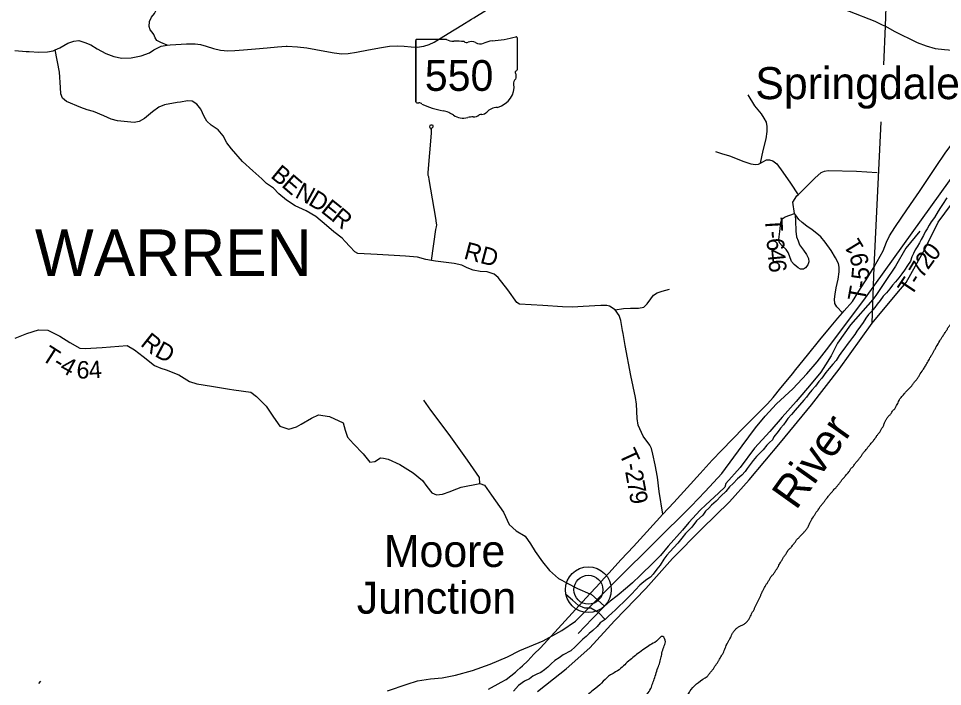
# Model space of a CAD drawing. Extents: x -84548 to 2262448, y -162180 to 525962.
# Drawn here: x 26368 to 42243, y 86581 to 98053 of the extents above; entities that cross this region are included whole.
import ezdxf

# ---------------------------------------------------------------- set-up
doc = ezdxf.new("R2010")
doc.units = 0
for name, color, linetype in [('GM_X_Adjacent_County_Text', 7, 'Continuous'), ('GM_X_City_Street', 7, 'Continuous'), ('GM_X_Corporation_Text', 7, 'Continuous'), ('GM_X_Hydro', 7, 'Continuous'), ('GM_X_Interstate_Location', 7, 'Continuous'), ('GM_X_Major_Lake_Text', 7, 'Continuous'), ('GM_X_Major_River', 7, 'Continuous'), ('GM_X_Minor_Lake', 7, 'Continuous'), ('GM_X_Rail_Line', 7, 'Continuous'), ('GM_X_State_Route', 7, 'Continuous'), ('GM_X_Township_Road', 7, 'Continuous'), ('GM_X_Township_ROW', 7, 'Continuous'), ('GM_X_Unincorporated_Location', 7, 'Continuous')]:
    doc.layers.add(name, color=color, linetype=linetype)

msp = doc.modelspace()

# ---------------------------------------------------------------- linework, layer by layer
at = {"layer": 'GM_X_City_Street'}
msp.add_line((41032, 92821), (41457, 93329), dxfattribs=at)
at = {"layer": 'GM_X_Hydro'}
for p, q in [((41265, 97920), (41693, 109574)), ((41234, 97255), (41265, 97920)), ((41070, 93787), (41188, 96276)), ((42169, 94557), (42676, 95246)), ((41940, 94093), (42169, 94557)), ((41616, 93517), (41940, 94093)), ((41032, 92821), (41070, 93787)), ((41457, 93329), (41616, 93517)), ((40467, 92029), (41032, 92821)), ((39990, 91416), (40467, 92029)), ((39460, 90770), (39990, 91416)), ((38921, 90130), (39460, 90770)), ((38585, 89751), (38921, 90130)), ((38110, 89287), (38585, 89751)), ((37603, 88778), (38110, 89287)), ((37145, 88264), (37603, 88778)), ((36609, 87712), (37145, 88264)), ((36186, 87243), (36609, 87712)), ((35780, 86887), (36186, 87243)), ((35558, 86715), (35780, 86887)), ((35286, 86497), (35558, 86715))]:
    msp.add_line(p, q, dxfattribs=at)
at = {"layer": 'GM_X_Interstate_Location'}
for points in [[(42315, 94974), (42241, 94857), (42207, 94806), (42168, 94747), (42106, 94638), (42051, 94563), (42012, 94506), (41977, 94439), (41946, 94387), (41917, 94328), (41876, 94259), (41847, 94198), (41810, 94130), (41774, 94079), (41745, 94018), (41718, 93958), (41695, 93885), (41644, 93812), (41588, 93731), (41543, 93670), (41492, 93599), (41435, 93532), (41386, 93475), (41339, 93412), (41282, 93343), (41226, 93282), (41174, 93208), (41120, 93147), (41081, 93089), (41026, 93024), (40973, 92969), (40926, 92906), (40879, 92831), (40834, 92768), (40773, 92684), (40738, 92628), (40699, 92573), (40644, 92504), (40603, 92453), (40564, 92396), (40527, 92345), (40466, 92264), (40415, 92181), (40360, 92116), (40295, 92041), (40238, 91972), (40168, 91876), (40120, 91817), (40062, 91740), (39997, 91671), (39948, 91608), (39906, 91553), (39859, 91500), (39789, 91413), (39710, 91325), (39649, 91254), (39588, 91185), (39553, 91134), (39510, 91075)], [(39510, 91075), (39460, 91020), (39419, 90961), (39347, 90870), (39323, 90819), (39272, 90774), (39227, 90724), (39160, 90648), (39103, 90589), (39050, 90532), (38991, 90461), (38936, 90392), (38885, 90327), (38852, 90276), (38793, 90209), (38721, 90146), (38647, 90068), (38583, 90009), (38521, 89930), (38440, 89858), (38353, 89767), (38272, 89695), (38227, 89644), (38174, 89595), (38125, 89526), (38018, 89426), (37936, 89316), (37881, 89263), (37829, 89210), (37765, 89127), (37696, 89044), (37627, 88970), (37560, 88895), (37509, 88836), (37454, 88767), (37390, 88664), (37335, 88595), (37270, 88511), (37225, 88458), (37165, 88419), (37110, 88378), (37041, 88319), (36968, 88244), (36907, 88174), (36848, 88113), (36759, 88026), (36694, 87964), (36617, 87893), (36566, 87844), (36498, 87785), (36445, 87734), (36364, 87674), (36311, 87613), (36236, 87544), (36171, 87494), (36123, 87442), (36062, 87392), (35993, 87327), (35930, 87262), (35859, 87195), (35727, 87125)], [(35727, 87125), (35656, 87076), (35580, 87030), (35517, 86971), (35464, 86912), (35408, 86868), (35343, 86823), (35275, 86792), (35205, 86761), (35146, 86711)], [(35146, 86711), (35062, 86674), (34958, 86601), (34871, 86500)]]:
    msp.add_lwpolyline(points, dxfattribs=at)
for points in [[(41241, 91094), (41263, 91144), (41287, 91185), (41320, 91229), (41360, 91271), (41382, 91311), (41422, 91350), (41446, 91394), (41481, 91454), (41497, 91495), (41531, 91545), (41583, 91605), (41616, 91646), (41672, 91698), (41716, 91745), (41744, 91789), (41785, 91837), (41821, 91884), (41847, 91928), (41907, 92018), (41944, 92077), (41976, 92131), (42006, 92183), (42028, 92224), (42057, 92276), (42081, 92318), (42107, 92361), (42137, 92415), (42196, 92515), (42226, 92564), (42254, 92606), (42287, 92658), (42315, 92699), (42337, 92741), (42371, 92789), (42400, 92831), (42434, 92890), (42470, 92940), (42508, 92997), (42543, 93045), (42575, 93089), (42607, 93132), (42637, 93174), (42665, 93216), (42692, 93256), (42726, 93303), (42754, 93343), (42794, 93401), (42824, 93442), (42855, 93482), (42891, 93522), (42927, 93573), (42975, 93627), (43008, 93669), (43048, 93724), (43088, 93774), (43154, 93863), (43185, 93907), (43231, 93965), (43267, 94010), (43317, 94068), (43358, 94115), (43410, 94171), (43450, 94213), (43480, 94254), (43522, 94278), (43563, 94318), (43611, 94355), (43653, 94393), (43721, 94464), (43765, 94500), (43808, 94550), (43852, 94605), (43884, 94653), (43930, 94721), (43967, 94770), (44033, 94858), (44077, 94911), (44111, 94955), (44140, 95001), (44176, 95042), (44210, 95084), (44256, 95134), (44296, 95173), (44335, 95213), (44389, 95264), (44433, 95310), (44473, 95354), (44513, 95397), (44558, 95445), (44606, 95493), (44656, 95542), (44706, 95590), (44747, 95629), (44787, 95665), (44845, 95713), (44891, 95752)], [(38202, 86755), (38234, 86797), (38268, 86839), (38307, 86886), (38331, 86928), (38363, 86970), (38387, 87010), (38413, 87051), (38460, 87131), (38484, 87175), (38502, 87220), (38518, 87262), (38535, 87304), (38559, 87348), (38585, 87391), (38611, 87439), (38628, 87485), (38656, 87525), (38694, 87570), (38738, 87604), (38782, 87628), (38824, 87647), (38870, 87681), (38909, 87725), (38935, 87766), (38955, 87808), (38971, 87852), (39001, 87892), (39020, 87937), (39042, 87983), (39064, 88029), (39109, 88122), (39129, 88168), (39151, 88216), (39175, 88260), (39196, 88301), (39222, 88343), (39248, 88383), (39278, 88431), (39302, 88472), (39337, 88512), (39367, 88556), (39395, 88597), (39423, 88643), (39443, 88683), (39474, 88735), (39498, 88778), (39530, 88824), (39564, 88874), (39595, 88927), (39635, 88965), (39673, 89013), (39711, 89058), (39735, 89098), (39778, 89142), (39820, 89187), (39860, 89225), (39894, 89267), (39928, 89310), (39951, 89366), (39973, 89412), (40025, 89493), (40054, 89543), (40080, 89583), (40118, 89630), (40144, 89674), (40182, 89720), (40213, 89760), (40245, 89803), (40287, 89855), (40323, 89899), (40360, 89942), (40408, 89996), (40446, 90039), (40484, 90083), (40516, 90133), (40557, 90178), (40599, 90226), (40643, 90280), (40671, 90323), (40713, 90367), (40746, 90417), (40792, 90468), (40826, 90512), (40856, 90554), (40887, 90599), (40929, 90649), (40963, 90691), (40995, 90732), (41041, 90786), (41072, 90826), (41110, 90879), (41140, 90919), (41172, 90961), (41193, 91004), (41223, 91048), (41241, 91094)], [(35751, 85218), (36117, 85474), (36217, 85576), (36310, 85654), (36386, 85744), (36466, 85853), (36547, 85943), (36634, 86004), (36756, 86093), (36859, 86157), (36948, 86202), (37035, 86268), (37101, 86357), (37185, 86471), (37242, 86572), (37272, 86663), (37308, 86757), (37342, 86876), (37381, 86973), (37405, 87067), (37423, 87154), (37454, 87259), (37482, 87349), (37436, 87442), (37328, 87360), (37219, 87296), (37126, 87231), (37009, 87146), (36925, 87077), (36826, 86999), (36740, 86913), (36627, 86831), (36540, 86782), (36416, 86671), (36290, 86555), (36197, 86481), (36079, 86379), (35970, 86303), (35879, 86245), (35795, 86124)], [(35799, 84357), (36082, 84623), (36161, 84710), (36247, 84796), (36340, 84874), (36440, 84970), (36538, 85065), (36621, 85155), (36761, 85280), (36877, 85356), (36962, 85421), (37060, 85519), (37139, 85607), (37215, 85696), (37296, 85784), (37403, 85908), (37480, 85997), (37556, 86101), (37658, 86215), (37754, 86317), (37862, 86435), (37925, 86528), (38202, 86755)]]:
    msp.add_spline(points, degree=3, dxfattribs=at)
at = {"layer": 'GM_X_Major_Lake_Text'}
for points in [[(34151, 98041), (34152, 98041), (34193, 98065), (34404, 98198), (34535, 98275), (34649, 98346), (34744, 98399), (34838, 98436), (34912, 98448), (34941, 98449)], [(39394, 98410), (39449, 98404), (39548, 98394), (39742, 98375), (39885, 98355), (39912, 98350), (40045, 98328), (40231, 98281), (40412, 98254), (40638, 98179), (41078, 98005), (41159, 97968)], [(30968, 97577), (30986, 97579), (31164, 97566), (31324, 97552), (31477, 97521), (31629, 97492), (31789, 97463), (31925, 97447), (32033, 97450), (32175, 97475), (32383, 97513), (32604, 97555), (32744, 97576), (32876, 97581), (32996, 97578), (33112, 97567), (33220, 97560), (33332, 97577), (33424, 97606), (33511, 97647), (33748, 97795), (33984, 97941), (34151, 98041)], [(41159, 97968), (41209, 97946)], [(41209, 97946), (41265, 97920), (41412, 97837), (41809, 97640), (41965, 97585), (42115, 97536), (42277, 97520), (42415, 97509), (42543, 97506), (42681, 97519), (42746, 97529), (42753, 97530)], [(26546, 97484), (26549, 97484), (26719, 97476), (26864, 97479), (26962, 97496), (27001, 97513), (27080, 97548), (27217, 97627), (27321, 97666), (27407, 97673), (27507, 97643), (27609, 97600), (27722, 97533), (27870, 97451), (28004, 97398), (28144, 97371), (28304, 97378), (28476, 97413), (28617, 97462), (28695, 97514), (28739, 97539), (28822, 97576), (28924, 97597), (28977, 97600)], [(26303, 97501), (26503, 97487), (26546, 97484)], [(28977, 97600), (28977, 97600), (29072, 97606), (29252, 97618), (29402, 97619), (29496, 97604), (29592, 97580), (29721, 97535), (29839, 97510), (29965, 97496), (30085, 97501), (30235, 97516), (30443, 97530), (30640, 97552), (30816, 97565), (30968, 97577)], [(41071, 93789), (41226, 94063), (41281, 94211), (41334, 94322), (41425, 94461), (41543, 94640), (41692, 94857), (41848, 95081), (41985, 95286), (42135, 95512), (42291, 95741), (42420, 95920), (42515, 96021), (42618, 96132), (42753, 96263), (42893, 96393), (43071, 96560), (43179, 96665), (43240, 96744), (43293, 96812), (43432, 96986), (43512, 97094), (43534, 97123)], [(39612, 91886), (39665, 91952), (39726, 92026), (39925, 92270), (40137, 92534), (40304, 92736), (40442, 92909), (40523, 92999), (40553, 93034), (40694, 93195), (40835, 93417), (40933, 93565), (41070, 93787), (41071, 93789)], [(36430, 88440), (36431, 88441), (36510, 88528), (36725, 88760), (36935, 88988), (37165, 89238), (37439, 89543), (37629, 89741), (37856, 89995), (38080, 90237), (38286, 90469), (38451, 90640), (38638, 90828), (38830, 91028), (39043, 91242), (39239, 91437), (39334, 91542), (39467, 91708), (39612, 91886)], [(34986, 86900), (35029, 86939), (35120, 87025), (35223, 87134), (35336, 87247), (36186, 88174), (36300, 88296), (36430, 88440)], [(34445, 86536), (34662, 86654), (34744, 86701), (34905, 86828), (34937, 86856), (34986, 86900)]]:
    msp.add_lwpolyline(points, dxfattribs=at)
at = {"layer": 'GM_X_Major_River'}
for radius in [393, 249]:
    msp.add_circle((36159, 88244), radius, dxfattribs=at)
at = {"layer": 'GM_X_Minor_Lake'}
for points in [[(28924, 97597), (28816, 97641), (28746, 97673), (28718, 97721), (28695, 97781), (28667, 97817), (28629, 97861), (28615, 97917), (28622, 98001), (28652, 98073), (28703, 98140), (28731, 98198), (28762, 98310), (28784, 98453), (28797, 98565), (28806, 98669), (28780, 98761), (28729, 98887), (28683, 98991), (28662, 99079), (28632, 99207), (28595, 99381), (28577, 99428)], [(29151, 96619), (29097, 96611), (28877, 96572), (28780, 96531), (28672, 96449), (28533, 96334), (28443, 96283), (28355, 96267), (28241, 96276), (28069, 96296), (27963, 96327), (27837, 96381), (27657, 96456), (27549, 96482), (27439, 96525), (27194, 96626), (27126, 96686), (27098, 96760), (27089, 96868), (27074, 97129), (27001, 97513)], [(31982, 94224), (31981, 94226), (31928, 94282), (31785, 94387), (31659, 94501), (31476, 94654), (31310, 94750), (31121, 94837), (30973, 94936), (30842, 95044), (30748, 95138), (30632, 95219), (30547, 95299), (30395, 95435), (30216, 95598), (30027, 95812), (29948, 95915), (29884, 96039), (29799, 96143), (29681, 96223), (29603, 96289), (29558, 96370), (29500, 96494), (29431, 96580), (29351, 96634), (29271, 96638), (29152, 96619), (29151, 96619)], [(40523, 92999), (40428, 93101), (40396, 93161), (40389, 93235), (40397, 93319), (40418, 93426), (40451, 93578), (40468, 93703), (40468, 93708), (40469, 93783), (40457, 93845), (40404, 93941), (40329, 94070), (40230, 94210), (40150, 94304), (40083, 94363), (40005, 94421), (39912, 94486), (39832, 94548), (39775, 94604), (39720, 94683), (39702, 94707), (39673, 94898), (39742, 95006), (39762, 95026), (40048, 95313), (40161, 95406), (40217, 95430), (40281, 95443), (40764, 95430), (41122, 95406)], [(39720, 94683), (39709, 94677), (39709, 94672), (39717, 94585), (39723, 94401), (39733, 94305), (39762, 94233), (39786, 94169), (39857, 94077), (39906, 93999), (39940, 93930), (39945, 93873), (39929, 93823), (39887, 93771), (39853, 93749), (39803, 93750), (39763, 93772), (39695, 93828), (39650, 93880), (39616, 93978), (39591, 94035), (39557, 94087), (39486, 94151), (39442, 94203), (39432, 94257), (39449, 94397), (39465, 94550), (39487, 94614), (39541, 94648), (39702, 94707)], [(41854, 94401), (41614, 94107), (41433, 93800), (41256, 93535), (41095, 93294)], [(36756, 92641), (36756, 92642), (36748, 92693), (36716, 92865), (36688, 92954), (36618, 93052), (36523, 93113), (36476, 93124), (36372, 93126), (36072, 93107), (35885, 93093), (35713, 93101), (35376, 93125), (34974, 93145), (34932, 93177), (34775, 93395), (34612, 93607), (34540, 93662), (34423, 93702), (34299, 93711), (34177, 93733), (34075, 93772), (33985, 93818), (33853, 93848), (33531, 93888), (33466, 93898), (33365, 93913), (33223, 93957), (33017, 93970), (32531, 93998), (32197, 94016), (32145, 94044), (32062, 94140), (31982, 94224)], [(41095, 93294), (41048, 93225), (40664, 92795), (40438, 92476), (40333, 92259), (40232, 92105), (40151, 91980), (39984, 91777), (39728, 91475), (39488, 91205), (39275, 90959), (39013, 90676), (38768, 90345), (38522, 90069), (38504, 90002), (38399, 89905), (38248, 89762), (38248, 89762)], [(26314, 92565), (26514, 92643), (26713, 92704), (26870, 92703), (27078, 92597), (27253, 92488), (27422, 92394), (27514, 92384), (27808, 92404), (28236, 92435), (28364, 92361), (28513, 92250), (28705, 92095), (28812, 92048), (28907, 92021), (29123, 91932), (29304, 91817), (29435, 91780), (29682, 91739), (29993, 91689), (30070, 91677), (30360, 91637), (30458, 91564), (30623, 91395), (30748, 91205), (30861, 91051), (31013, 91000), (31146, 91039), (31227, 91087), (31405, 91191), (31525, 91246), (31712, 91216), (31946, 91110), (31981, 90986), (32018, 90865), (32126, 90751), (32292, 90576), (32404, 90432), (32490, 90447), (32590, 90508), (32639, 90505), (32721, 90484), (32922, 90392), (33147, 90248), (33310, 90117), (33385, 90015), (33467, 89910), (33548, 89872), (33652, 89882), (33783, 89933), (33824, 89949), (33974, 90007), (34297, 90066), (34376, 90037), (34492, 89869), (34703, 89577), (34799, 89362), (34918, 89252), (35076, 89165), (35163, 89029), (35246, 88898), (35370, 88724), (35492, 88572), (35647, 88437), (35703, 88407), (35783, 88364), (35975, 88267), (36186, 88174), (36206, 88166), (36434, 87962)], [(37439, 89543), (37378, 89932), (37345, 90178), (37306, 90391), (37264, 90571), (37242, 90666), (37213, 90724), (37101, 90878), (37013, 91070), (36997, 91186), (36985, 91432), (36969, 91544), (36887, 91921), (36789, 92437), (36756, 92641)], [(38248, 89762), (38179, 89699), (38081, 89609), (37884, 89396), (37775, 89269), (37531, 88989), (37400, 88830), (37280, 88710), (37048, 88486)], [(37048, 88486), (36920, 88363), (36833, 88289)], [(36833, 88289), (36654, 88137), (36534, 88048), (36434, 87962), (36225, 87743)], [(36225, 87743), (35983, 87490)]]:
    msp.add_lwpolyline(points, dxfattribs=at)
at = {"layer": 'GM_X_Rail_Line'}
for p, q in [((33196, 97677), (33196, 96621)), ((33196, 96621), (33196, 97677)), ((33196, 96621), (33196, 97677)), ((33213, 97696), (33723, 97696)), ((34936, 97722), (34936, 97169)), ((34936, 97169), (34936, 97169))]:
    msp.add_line(p, q, dxfattribs=at)
for centre, major_axis, start_param, end_param in [((33216, 97680), (20.2, 0), 1.712693, 3.28349), ((33844, 97818), (196, 0), 4.042523, 4.731795), ((33909, 97102), (702, 0), 1.404758, 1.657858), ((34068, 97685), (56.4, 0), 3.836095, 5.185415), ((34151, 97563), (117, 0), 0.950623, 2.079405), ((34302, 97731), (141, 0), 4.081561, 5.145723), ((34552, 97373), (371, 0), 1.699011, 2.107814), ((34316, 99136), (1845, 0), 4.814394, 5.042369), ((34917, 97724), (19.4, 0), 6.141152, 7.989035), ((34915, 97167), (20.7, 0), 5.05454, 6.418171), ((35005, 96938), (131, 0), 2.387724, 3.262537), ((34932, 97129), (30, 0), 1.883978, 3.671073), ((34741, 97059), (180, 0), 5.934695, 6.695948), ((34420, 96867), (462, 0), 5.101752, 6.440018), ((33216, 96619), (20.3, 0), 3.00124, 4.508301), ((33219, 96727), (155, 0), 4.665946, 4.897461), ((33251, 96560), (56, 0), 0.519207, 1.627899), ((33957, 97509), (1333, 0), 4.195997, 4.488961), ((34614, 96324), (253, 0), 1.647645, 2.488434), ((33560, 96146), (417, 0), 0.823519, 1.323587), ((34011, 96555), (265, 0), 4.026481, 4.996735), ((34164, 96189), (217, 0), 1.495662, 1.94098), ((34183, 96475), (141, 0), 4.691044, 5.507374), ((34311, 96373), (39.7, 0), 1.147584, 2.315152), ((34294, 96518), (149, 0), 4.937069, 5.64225)]:
    msp.add_ellipse(centre, major_axis=major_axis, ratio=0.8, start_param=start_param, end_param=end_param, dxfattribs=at)
at = {"layer": 'GM_X_State_Route'}
for points in [[(36445, 87734), (36340, 87846), (36202, 87924), (36098, 87928), (35992, 87974), (35886, 88063), (35770, 88159)], [(26744, 86671), (26712, 86635)]]:
    msp.add_lwpolyline(points, dxfattribs=at)
at = {"layer": 'GM_X_Township_ROW'}
for points in [[(39114, 95569), (39160, 95786), (39213, 95989), (39232, 96115), (39229, 96199), (39217, 96271), (39182, 96341), (39136, 96415), (39017, 96554), (38905, 96744)], [(33466, 93898), (33536, 94430), (33547, 94476), (33554, 94511), (33547, 94539), (33536, 94624), (33423, 95289), (33419, 95332), (33409, 95356), (33409, 95409), (33462, 96085), (33462, 96135), (33460, 96154), (33470, 96169), (33490, 96195), (33490, 96216), (33476, 96223), (33451, 96223), (33433, 96213), (33430, 96195), (33437, 96181), (33454, 96167), (33458, 96163), (33469, 96170)], [(38344, 95771), (38449, 95736)], [(38449, 95736), (38583, 95692), (38828, 95599), (38948, 95558), (39028, 95543), (39078, 95551), (39083, 95553), (39114, 95569), (39158, 95592), (39222, 95624), (39273, 95628), (39328, 95607), (39398, 95557), (39499, 95415), (39631, 95226), (39762, 95026)], [(36618, 93052), (36763, 93073), (36885, 93078), (37021, 93077), (37111, 93096), (37167, 93154), (37234, 93241), (37276, 93301), (37343, 93344), (37429, 93370), (37551, 93407)], [(34297, 90066), (34287, 90170), (34080, 90471), (33768, 90910), (33453, 91326), (33331, 91496)]]:
    msp.add_lwpolyline(points, dxfattribs=at)
at = {"layer": 'GM_X_Unincorporated_Location'}
for points in [[(36665, 88430), (37924, 89678), (38164, 89933), (38450, 90238), (38801, 90715), (39028, 91026), (39198, 91223), (39392, 91435), (39670, 91694), (39915, 91951), (40092, 92158), (40291, 92417), (40922, 93255), (42523, 95488)], [(32707, 86507), (33044, 86621), (33221, 86678), (33448, 86713), (33648, 86728), (33879, 86776), (34166, 86855), (34469, 86966), (34770, 87093), (34979, 87202), (35382, 87363), (35702, 87546), (35937, 87705), (36320, 88089), (36665, 88430)]]:
    msp.add_lwpolyline(points, dxfattribs=at)

# ---------------------------------------------------------------- texts
at = {"layer": 'GM_X_Adjacent_County_Text'}
for s, rotation, p in [('Springdale', 0, (39027, 96668)), ('River', 54.5766, (39726, 89596)), ('Moore', 0, (32646, 88635)), ('Junction', 0, (32180, 87832))]:
    msp.add_text(s, height=550, rotation=rotation, dxfattribs=at).set_placement(p)
at = {"layer": 'GM_X_Corporation_Text'}
msp.add_text('WARREN', height=800, rotation=0, dxfattribs=at).set_placement((26651, 93631))
at = {"layer": 'GM_X_Rail_Line'}
msp.add_text('550', height=528, dxfattribs=at).set_placement((33349, 96810))
at = {"layer": 'GM_X_Township_Road'}
for s, rotation, p in [('B', 320.4618, (30685, 95332)), ('E', 319.1644, (30873, 95176)), ('N', 331.8377, (31102, 94989)), ('D', 329.1006, (31331, 94866)), ('E', 321.3984, (31549, 94737)), ('R', 320.3603, (31723, 94598)), ('T', 273.4734, (39192, 94626)), ('-', 274.7431, (39206, 94395)), ('RD', 345.1318, (34004, 93933)), ('6', 275.1202, (39217, 94270)), ('1', 121.2465, (40905, 94117)), ('0', 50.0608, (42097, 93872)), ('4', 275.4331, (39233, 94084)), ('9', 101.8868, (40983, 93834)), ('2', 54.3062, (41993, 93726)), ('6', 275.508, (39251, 93900)), ('7', 59.2796, (41902, 93573)), ('5', 84.8688, (40973, 93553)), ('-', 80.2428, (40948, 93405)), ('T', 56.2374, (41702, 93268)), ('-', 57.4996, (41830, 93461)), ('T', 79.6411, (40907, 93181)), ('R', 321.5258, (28449, 92446)), ('T', 327.4095, (26744, 92201)), ('D', 332.1761, (28692, 92260)), ('-', 329.2429, (26942, 92075)), ('4', 331.1459, (27057, 92006)), ('6', 356.6895, (27358, 91877)), ('4', 4.2837, (27586, 91867)), ('T', 294.5369, (36680, 90583)), ('-', 280.2015, (36767, 90397)), ('2', 280.3393, (36789, 90275)), ('7', 280.3856, (36823, 90093)), ('9', 280.3977, (36856, 89911))]:
    msp.add_text(s, height=300, rotation=rotation, dxfattribs=at).set_placement(p)

doc.saveas('drawing.dxf')
